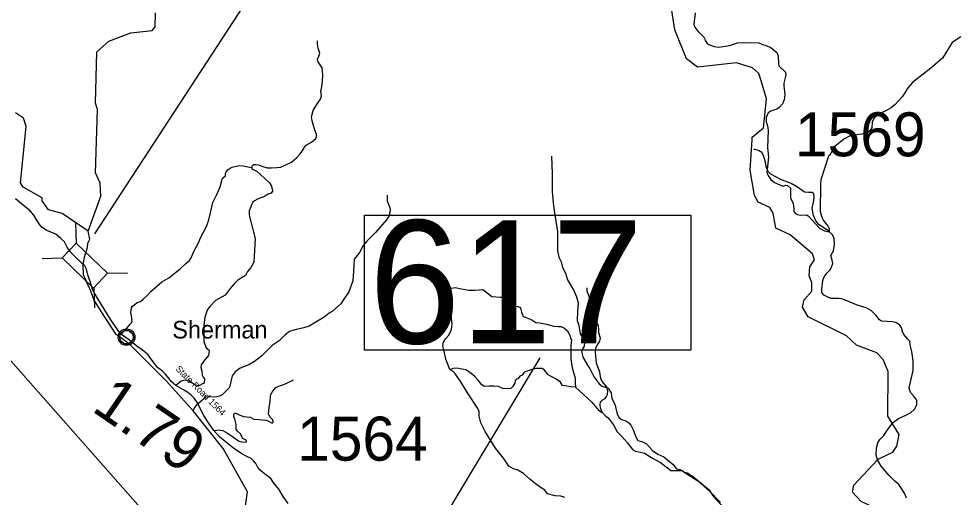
# Model space of a CAD drawing. Extents: x 1248224 to 1454986, y 825081 to 985870.
# Drawn here: x 1308155 to 1318874, y 948203 to 953644 of the extents above; entities that cross this region are included whole.
import ezdxf

# ---------------------------------------------------------------- set-up
doc = ezdxf.new("R2010")
doc.units = 0
for name, color, linetype in [('Exist Civil Demographics Community CELL', 7, 'Continuous'), ('Exist Civil Demographics Community Label', 7, 'Continuous'), ('Exist Hydrographic Creek Single Shore', 7, 'Continuous'), ('Exist Hydrographic Misc Water Feature', 7, 'Continuous'), ('Exist Road Non-System Type 51', 7, 'Continuous'), ('Exist Road Secondary Mileage Hundredths English Label', 7, 'Continuous'), ('Exist Road Secondary Structure Standard Bridge CELL', 7, 'Continuous'), ('Exist Road Secondary Structure Standard Bridge Number Label', 7, 'Continuous'), ('Exist Road Secondary Type 10 Attributed', 7, 'Continuous'), ('Exist Road Secondary Type 51 Attributed', 7, 'Continuous'), ('Exist Road Secondary Type 51 Label', 7, 'Continuous'), ('Exist Road Secondary Type 51 Number Label', 7, 'Continuous')]:
    doc.layers.add(name, color=color, linetype=linetype)

msp = doc.modelspace()

# ---------------------------------------------------------------- linework, layer by layer
at = {"layer": 'Exist Civil Demographics Community CELL'}
msp.add_lwpolyline([(1309304, 950035), (1309305, 950041), (1309307, 950047), (1309310, 950055), (1309313, 950060), (1309316, 950066), (1309320, 950071), (1309324, 950075), (1309328, 950080), (1309334, 950085), (1309339, 950088), (1309344, 950091), (1309349, 950094), (1309355, 950096), (1309360, 950098), (1309365, 950099), (1309369, 950100), (1309374, 950100), (1309380, 950101), (1309384, 950101), (1309390, 950100), (1309395, 950100), (1309400, 950099), (1309405, 950097), (1309410, 950095), (1309417, 950092), (1309423, 950089), (1309428, 950085), (1309433, 950081), (1309436, 950078), (1309441, 950074), (1309444, 950069), (1309448, 950064), (1309451, 950059), (1309453, 950054), (1309455, 950049), (1309457, 950044), (1309458, 950040), (1309459, 950034), (1309460, 950029), (1309460, 950023), (1309460, 950017), (1309459, 950011), (1309458, 950006), (1309457, 950000), (1309455, 949994), (1309452, 949989), (1309449, 949983), (1309446, 949978), (1309443, 949973), (1309438, 949968), (1309433, 949963), (1309428, 949959), (1309423, 949956), (1309419, 949953), (1309412, 949950), (1309405, 949947), (1309399, 949946), (1309392, 949944), (1309388, 949944), (1309383, 949944), (1309378, 949944), (1309373, 949944), (1309368, 949945), (1309362, 949946), (1309357, 949947), (1309352, 949949), (1309347, 949951), (1309344, 949954), (1309337, 949958), (1309331, 949962), (1309326, 949966), (1309322, 949971), (1309319, 949975), (1309316, 949979), (1309312, 949986), (1309310, 949990), (1309308, 949994), (1309306, 950002), (1309304, 950009), (1309303, 950014), (1309303, 950021), (1309303, 950025), (1309303, 950032)], close=True, dxfattribs=at)
for centre, radius in [((1309382, 950023), 94.3), ((1309381, 950023), 76.7)]:
    msp.add_circle(centre, radius, dxfattribs=at)
at = {"layer": 'Exist Hydrographic Creek Single Shore'}
for points in [[(1316504, 952267), (1316507, 952297), (1316634, 952403), (1316667, 952733), (1316613, 952928), (1316582, 953021), (1316508, 953088), (1316326, 953144), (1315883, 953094), (1315759, 953188), (1315625, 953519), (1315560, 953937)], [(1308944, 951228), (1308649, 951428), (1308492, 951473), (1308419, 951573), (1308420, 951606), (1308206, 951729), (1308173, 951778), (1308238, 952421), (1308207, 952513), (1308117, 952574)], [(1318070, 949093), (1318051, 949124), (1318054, 949633), (1317999, 949769), (1317926, 949845), (1317694, 949932), (1317580, 950036), (1317143, 950255), (1317079, 950365), (1317097, 950446), (1317183, 950547), (1317186, 950645), (1317154, 950721), (1317164, 950823), (1317217, 950904), (1317193, 950970), (1316939, 951185), (1316775, 951264), (1316745, 951432), (1316705, 951498), (1316573, 951560), (1316533, 951636), (1316481, 951923), (1316504, 952267)], [(1308887, 950849), (1308902, 950934), (1308935, 951044), (1308941, 951092), (1308964, 951139), (1308944, 951228)], [(1309262, 950054), (1309098, 950312), (1309007, 950452), (1308974, 950547), (1308892, 950733), (1308887, 950849)], [(1311047, 947831), (1310858, 948058), (1310733, 948077), (1310757, 948262), (1310481, 948756), (1310139, 949185), (1309835, 949522), (1309411, 949947), (1309262, 950054)], [(1317921, 947117), (1317896, 947134), (1317947, 947534), (1318087, 947807), (1318114, 947915), (1318050, 948008), (1317745, 948155), (1317647, 948259), (1317665, 948340), (1317879, 948570), (1317939, 948634), (1318041, 948683), (1318108, 948716), (1318151, 948781), (1318179, 948915), (1318070, 949093)]]:
    msp.add_lwpolyline(points, dxfattribs=at)
at = {"layer": 'Exist Hydrographic Misc Water Feature'}
for points in [[(1308944, 951228), (1309087, 951626), (1309082, 951773), (1309027, 951893), (1309052, 952611), (1309028, 952684), (1309042, 953268), (1309178, 953390), (1309431, 953483), (1309673, 953511), (1309707, 953553), (1309711, 953711)], [(1315858, 953711), (1315841, 953580), (1315853, 953548), (1315888, 953503), (1315962, 953429), (1315969, 953397), (1315998, 953360), (1316018, 953347), (1316074, 953330), (1316126, 953323), (1316246, 953340), (1316337, 953372), (1316501, 953376), (1316581, 953370), (1316635, 953347), (1316654, 953346), (1316718, 953317), (1316785, 953263), (1316800, 953223), (1316806, 953134), (1316811, 953111), (1316885, 953037), (1316889, 953005), (1316867, 952913), (1316866, 952881), (1316877, 952783), (1316868, 952723), (1316851, 952676), (1316814, 952636), (1316786, 952617), (1316719, 952595), (1316686, 952573), (1316665, 952522), (1316664, 952473), (1316679, 952425), (1316686, 952373), (1316679, 952181), (1316691, 952071), (1316671, 951895), (1316686, 951862), (1316719, 951818), (1316758, 951781), (1316853, 951742), (1316890, 951752), (1316909, 951747), (1316941, 951718), (1316942, 951608), (1316971, 951544), (1316981, 951484), (1316981, 951452), (1317008, 951422), (1317052, 951412), (1317124, 951414), (1317144, 951402), (1317271, 951263), (1317330, 951233), (1317382, 951220)], [(1318880, 953438), (1318783, 953373), (1318673, 953197), (1318540, 953082), (1318332, 952921), (1318266, 952844), (1318260, 952826), (1318214, 952756), (1318132, 952671), (1318087, 952633), (1318020, 952592), (1317959, 952566), (1317902, 952521), (1317898, 952522), (1317873, 952471), (1317867, 952403), (1317847, 952370), (1317820, 952347), (1317756, 952332), (1317667, 952322), (1317615, 952309), (1317550, 952275), (1317448, 952193), (1317388, 952093), (1317376, 952081), (1317287, 951813), (1317282, 951765), (1317281, 951451), (1317296, 951398), (1317315, 951354), (1317371, 951282), (1317382, 951258), (1317382, 951220)], [(1314219, 952081), (1314228, 951879), (1314227, 951679), (1314242, 951514), (1314289, 951220), (1314290, 951003), (1314304, 950934), (1314329, 950878), (1314347, 950814), (1314378, 950752), (1314404, 950676), (1314475, 950554), (1314506, 950481), (1314524, 950413), (1314516, 950315), (1314514, 950211), (1314529, 950171), (1314548, 950066), (1314556, 950046), (1314583, 950010), (1314598, 949965), (1314593, 949922), (1314562, 949870), (1314576, 949795), (1314641, 949684), (1314657, 949668), (1314705, 949566), (1314763, 949493), (1314798, 949464), (1314866, 949443), (1314901, 949389), (1314909, 949325), (1314940, 949260), (1314969, 949147), (1314986, 949112), (1315018, 949087), (1315065, 949069), (1315101, 949049), (1315124, 949020), (1315151, 948967), (1315181, 948887), (1315202, 948846), (1315250, 948837), (1315301, 948808), (1315372, 948732), (1315431, 948691), (1315498, 948661), (1315606, 948575), (1315645, 948526), (1315685, 948517), (1315736, 948485), (1315768, 948479)], [(1314219, 952081), (1314228, 951879), (1314227, 951679), (1314242, 951514), (1314289, 951220), (1314290, 951003), (1314304, 950934), (1314329, 950878), (1314347, 950814), (1314378, 950752), (1314404, 950676), (1314475, 950554), (1314506, 950481), (1314524, 950413), (1314516, 950315), (1314514, 950211), (1314529, 950171), (1314548, 950066), (1314556, 950046), (1314583, 950010), (1314598, 949965), (1314593, 949922), (1314562, 949870), (1314576, 949795), (1314641, 949684), (1314657, 949668), (1314705, 949566), (1314763, 949493), (1314798, 949464), (1314866, 949443), (1314901, 949389), (1314909, 949325), (1314940, 949260), (1314969, 949147), (1314986, 949112), (1315018, 949087), (1315065, 949069), (1315101, 949049), (1315124, 949020), (1315151, 948967), (1315181, 948887), (1315202, 948846), (1315250, 948837), (1315301, 948808), (1315372, 948732), (1315431, 948691), (1315498, 948661), (1315606, 948575), (1315645, 948526), (1315685, 948517), (1315736, 948485), (1315768, 948479)], [(1312348, 951637), (1312348, 951568), (1312375, 951510), (1312382, 951470), (1312372, 951406), (1312341, 951359), (1312218, 951212), (1312117, 951114), (1312068, 951054), (1312042, 950998), (1312009, 950951), (1311972, 950911), (1311967, 950773), (1311957, 950662), (1311912, 950539), (1311849, 950442), (1311820, 950403), (1311724, 950313), (1311688, 950296), (1311631, 950249), (1311460, 950147), (1311402, 950128), (1311313, 950110), (1311237, 950086), (1311188, 950051), (1311118, 949980), (1311041, 949928), (1310920, 949809), (1310838, 949747), (1310774, 949708), (1310677, 949669), (1310618, 949630), (1310585, 949583), (1310553, 949449), (1310469, 949367), (1310441, 949352), (1310409, 949343), (1310285, 949341), (1310174, 949246), (1310150, 949218), (1310139, 949185)], [(1315768, 948479), (1315776, 948476), (1315788, 948465), (1315823, 948447), (1316014, 948287), (1316056, 948218), (1316158, 948113)]]:
    msp.add_lwpolyline(points, dxfattribs=at)
at = {"layer": 'Exist Road Non-System Type 51'}
for points in [[(1310807, 951953), (1310811, 951969), (1310829, 951987), (1310855, 951987), (1310884, 951982), (1310933, 951963), (1310984, 951949), (1311031, 951948), (1311094, 951953), (1311137, 951958), (1311195, 951984), (1311258, 952014), (1311319, 952067), (1311356, 952103), (1311383, 952138), (1311391, 952159), (1311406, 952186), (1311427, 952208), (1311488, 952242), (1311537, 952284), (1311545, 952303), (1311545, 952331), (1311524, 952379), (1311495, 952482), (1311489, 952531), (1311508, 952603), (1311539, 952659), (1311571, 952702), (1311591, 952730), (1311600, 952763), (1311594, 952820), (1311606, 952874), (1311613, 952931), (1311618, 953009), (1311609, 953085), (1311564, 953155), (1311557, 953184), (1311571, 953221), (1311581, 953252), (1311565, 953310), (1311556, 953355), (1311557, 953395)], [(1309313, 950061), (1309330, 950069), (1309366, 950101), (1309427, 950173), (1309440, 950189), (1309444, 950207), (1309442, 950242), (1309431, 950303), (1309436, 950355), (1309451, 950377), (1309474, 950396), (1309503, 950416), (1309542, 950430), (1309572, 950454), (1309624, 950506), (1309658, 950542), (1309784, 950653), (1309861, 950697), (1309991, 950799), (1310056, 950861), (1310097, 950893), (1310118, 950926), (1310138, 950971), (1310158, 951020), (1310195, 951089), (1310228, 951162), (1310256, 951219), (1310293, 951280), (1310317, 951358), (1310338, 951439), (1310362, 951554), (1310407, 951639), (1310448, 951733), (1310472, 951819), (1310491, 951843), (1310510, 951858), (1310507, 951880), (1310515, 951904), (1310537, 951930), (1310560, 951946), (1310584, 951956), (1310628, 951967), (1310671, 951976), (1310712, 951973), (1310764, 951960), (1310807, 951953)], [(1310807, 951953), (1310808, 951942), (1310822, 951929), (1310869, 951908), (1310954, 951831), (1311008, 951777), (1311030, 951747), (1311039, 951710), (1311043, 951683), (1311030, 951661), (1310993, 951648), (1310944, 951618), (1310898, 951603), (1310871, 951592), (1310838, 951573), (1310819, 951557), (1310805, 951528), (1310795, 951504), (1310779, 951459), (1310779, 951419), (1310785, 951381), (1310846, 951144)], [(1310846, 951144), (1310840, 951012), (1310831, 950875), (1310797, 950814), (1310757, 950769), (1310737, 950724), (1310692, 950696), (1310643, 950667), (1310611, 950635), (1310562, 950578), (1310505, 950500), (1310395, 950439), (1310330, 950370), (1310301, 950329), (1310273, 950247), (1310260, 950162), (1310260, 950035), (1310260, 949974), (1310289, 949901), (1310321, 949876), (1310313, 949815), (1310269, 949762), (1310232, 949709), (1310228, 949678), (1310239, 949636), (1310241, 949591), (1310254, 949568), (1310270, 949547), (1310266, 949500), (1310259, 949497), (1310248, 949490), (1310205, 949470), (1310167, 949475), (1310117, 949506), (1310083, 949527), (1310055, 949532), (1310035, 949531), (1310004, 949524), (1309941, 949471)], [(1314371, 948197), (1314326, 948213), (1314263, 948217), (1314175, 948242), (1314143, 948283), (1314067, 948330), (1313972, 948407), (1313902, 948472), (1313837, 948511), (1313789, 948524), (1313735, 948556), (1313672, 948648), (1313584, 948761), (1313465, 948949), (1313415, 949049), (1313395, 949123), (1313395, 949177), (1313382, 949211), (1313271, 949378), (1313179, 949525), (1313127, 949602), (1313098, 949634), (1313062, 949654), (1313044, 949704), (1313017, 949772), (1312999, 949864), (1312983, 949925), (1312992, 949966), (1313014, 950002), (1313053, 950047), (1313082, 950110), (1313091, 950169), (1313077, 950275), (1313048, 950370), (1313028, 950399), (1313026, 950445), (1313026, 950477), (1313037, 950522), (1313059, 950558), (1313080, 950579), (1313125, 950588), (1313197, 950572), (1313280, 950556), (1313348, 950558), (1313398, 950563), (1313434, 950565), (1313465, 950545), (1313508, 950511), (1313542, 950486), (1313637, 950477), (1313695, 950477), (1313761, 950452)], [(1314796, 949167), (1314777, 949219), (1314775, 949256), (1314779, 949287), (1314799, 949307), (1314831, 949326), (1314847, 949346), (1314858, 949371), (1314863, 949414), (1314849, 949459), (1314797, 949517), (1314781, 949554), (1314770, 949626), (1314732, 949725), (1314721, 949847), (1314725, 949903), (1314743, 949937), (1314770, 949976), (1314777, 950012), (1314761, 950073), (1314759, 950109), (1314757, 950157), (1314734, 950190), (1314705, 950227), (1314687, 950274), (1314687, 950308), (1314689, 950362), (1314662, 950452), (1314626, 950547), (1314626, 950583)], [(1313761, 950452), (1313768, 950425), (1313786, 950400), (1313801, 950375), (1313838, 950373), (1313867, 950360), (1313869, 950353), (1313878, 950308), (1313896, 950256), (1313921, 950251), (1313995, 950220), (1314043, 950188), (1314088, 950186), (1314165, 950170), (1314248, 950147), (1314302, 950145), (1314327, 950145), (1314356, 950132), (1314397, 950098), (1314430, 950044), (1314436, 950015), (1314450, 949988), (1314441, 949932), (1314439, 949866), (1314441, 949771), (1314457, 949674), (1314488, 949555), (1314491, 949503), (1314495, 949453)], [(1314495, 949453), (1314436, 949458), (1314394, 949464), (1314344, 949473), (1314324, 949510), (1314274, 949546), (1314231, 949568), (1314182, 949595), (1314139, 949647), (1314116, 949665), (1314089, 949668), (1314048, 949665), (1313997, 949656), (1313967, 949645), (1313922, 949629), (1313902, 949613), (1313886, 949589), (1313861, 949580), (1313852, 949566), (1313836, 949550), (1313818, 949543), (1313807, 949528), (1313803, 949498), (1313780, 949460), (1313758, 949437), (1313728, 949433), (1313667, 949440), (1313615, 949462), (1313564, 949464), (1313509, 949464), (1313455, 949462), (1313427, 949479), (1313384, 949535), (1313348, 949576), (1313287, 949623), (1313244, 949650), (1313199, 949659), (1313167, 949666), (1313115, 949671), (1313062, 949654)], [(1310377, 948962), (1310408, 948964), (1310426, 948969), (1310479, 948960), (1310531, 948929), (1310586, 948892), (1310634, 948857), (1310663, 948841), (1310709, 948828), (1310746, 948833), (1310742, 948850), (1310707, 948868), (1310691, 948896), (1310683, 948921), (1310646, 948953), (1310628, 948977), (1310628, 949030), (1310613, 949089), (1310604, 949116), (1310604, 949136), (1310610, 949157), (1310624, 949158), (1310665, 949140), (1310713, 949122), (1310790, 949114), (1310830, 949090), (1310889, 949087), (1310968, 949079), (1310973, 949079), (1310999, 949068), (1311039, 949044), (1311052, 949056), (1311047, 949081), (1311012, 949116), (1310997, 949149), (1311006, 949221), (1311017, 949287), (1311021, 949355), (1311025, 949371), (1311041, 949397), (1311063, 949427), (1311083, 949450), (1311103, 949463), (1311151, 949476), (1311199, 949494), (1311283, 949538)], [(1314495, 949453), (1314581, 949373), (1314678, 949285), (1314755, 949192), (1314796, 949167)], [(1314796, 949167), (1314833, 949130), (1314869, 949103), (1314900, 949060), (1314934, 949015), (1314966, 948950), (1315022, 948891), (1315085, 948819), (1315128, 948762), (1315148, 948740), (1315173, 948724), (1315234, 948715), (1315281, 948704), (1315372, 948645), (1315462, 948595), (1315557, 948525), (1315581, 948507), (1315638, 948507), (1315710, 948505), (1315744, 948478), (1315886, 948388), (1316021, 948272), (1316143, 948142)]]:
    msp.add_lwpolyline(points, dxfattribs=at)
at = {"layer": 'Exist Road Secondary Structure Standard Bridge CELL'}
for p, q in [((1308801, 951318), (1308807, 951091)), ((1308421, 950918), (1308647, 950924)), ((1309165, 950749), (1309392, 950754)), ((1309009, 950585), (1309015, 950358))]:
    msp.add_line(p, q, dxfattribs=at)
msp.add_lwpolyline([(1308807, 951091), (1309166, 950749), (1309006, 950582), (1308647, 950924)], close=True, dxfattribs=at)
at = {"layer": 'Exist Road Secondary Structure Standard Bridge Number Label'}
msp.add_line((1309019, 951197), (1312285, 956192), dxfattribs=at)
for points in [[(1311436, 945141), (1311012, 946414), (1306982, 950975), (1306487, 954475)], [(1311311, 947403), (1311959, 947293), (1312875, 947766), (1314091, 949788)]]:
    msp.add_lwpolyline(points, dxfattribs=at)
msp.add_lwpolyline([(1312091, 951409), (1315807, 951409), (1315807, 949873), (1312091, 949873)], close=True, dxfattribs=at)
at = {"layer": 'Exist Road Secondary Type 10 Attributed'}
for points in [[(1318065, 948448), (1317973, 948557), (1317932, 948629), (1317919, 948679), (1317920, 948763), (1317935, 948819), (1317961, 948858), (1318005, 948904), (1318055, 948981), (1318116, 949054), (1318170, 949099), (1318256, 949135), (1318310, 949163), (1318355, 949204), (1318381, 949251), (1318379, 949307), (1318346, 949351), (1318307, 949394), (1318294, 949447), (1318317, 949544), (1318337, 949643), (1318340, 949753), (1318322, 949860), (1318304, 949936), (1318299, 949977), (1318276, 950002), (1318232, 950053), (1318216, 950086), (1318206, 950130), (1318187, 950161), (1318143, 950191), (1318099, 950199), (1318041, 950202), (1317979, 950203), (1317955, 950218), (1317912, 950273), (1317861, 950326), (1317804, 950358), (1317711, 950383), (1317537, 950456), (1317493, 950464), (1317403, 950464), (1317358, 950481), (1317323, 950502), (1317298, 950531), (1317300, 950570), (1317311, 950667), (1317326, 950709), (1317359, 950753), (1317394, 950787), (1317414, 950829), (1317423, 950862), (1317415, 950898), (1317402, 950950), (1317430, 951006), (1317443, 951077), (1317438, 951149), (1317418, 951191), (1317368, 951238), (1317268, 951302), (1317230, 951347), (1317203, 951405), (1317189, 951485), (1317209, 951578), (1317212, 951620), (1317209, 951655), (1317190, 951668), (1317146, 951667), (1317100, 951674), (1317021, 951728), (1316950, 951772), (1316831, 951816), (1316718, 951876), (1316684, 951910), (1316665, 951963), (1316658, 952015), (1316635, 952089), (1316616, 952122), (1316577, 952145), (1316524, 952163)], [(1318264, 948191), (1318244, 948240), (1318214, 948288), (1318176, 948346), (1318131, 948385), (1318065, 948448)]]:
    msp.add_lwpolyline(points, dxfattribs=at)
at = {"layer": 'Exist Road Secondary Type 51 Attributed'}
for points in [[(1308887, 950849), (1308772, 950958), (1308740, 950996), (1308706, 951047), (1308676, 951109), (1308634, 951145), (1308575, 951194), (1308473, 951236), (1308419, 951270), (1308393, 951302), (1308364, 951346), (1308324, 951410), (1308285, 951461), (1308184, 951541), (1308116, 951597)], [(1311221, 948130), (1311166, 948210), (1311117, 948293), (1311052, 948374), (1311024, 948414), (1310994, 948439), (1310954, 948469), (1310903, 948509), (1310877, 948540), (1310855, 948586), (1310828, 948616), (1310802, 948644), (1310752, 948665), (1310694, 948697), (1310601, 948760), (1310504, 948834), (1310440, 948889), (1310377, 948962), (1310315, 949048), (1310261, 949132), (1310231, 949189), (1310189, 949274), (1310153, 949327), (1310119, 949361), (1310081, 949393), (1310022, 949427), (1309941, 949471), (1309889, 949517), (1309861, 949557), (1309823, 949604), (1309789, 949634), (1309734, 949676), (1309698, 949723), (1309662, 949771), (1309626, 949822), (1309561, 949877), (1309497, 949922), (1309414, 949990), (1309313, 950061), (1309277, 950108), (1309203, 950218), (1309135, 950330), (1309040, 950485), (1308994, 950564), (1308971, 950645), (1308941, 950732), (1308926, 950797), (1308905, 950833), (1308887, 950849)]]:
    msp.add_lwpolyline(points, dxfattribs=at)

# ---------------------------------------------------------------- texts
at = {"layer": 'Exist Civil Demographics Community Label'}
msp.add_text('Sherman', height=200, dxfattribs=at).set_placement((1309902, 950008))
at = {"layer": 'Exist Road Secondary Mileage Hundredths English Label'}
msp.add_text('1.79', height=500, rotation=325.6899, dxfattribs=at).set_placement((1308971, 949190))
at = {"layer": 'Exist Road Secondary Structure Standard Bridge Number Label'}
msp.add_text('617', height=1400, dxfattribs=at).set_placement((1312141, 949952))
at = {"layer": 'Exist Road Secondary Type 51 Label'}
msp.add_text('State Road 1564', height=75, rotation=314.9302, dxfattribs=at).set_placement((1309934, 949655))
at = {"layer": 'Exist Road Secondary Type 51 Number Label'}
for s, p in [('1569', (1316993, 952080)), ('1564', (1311324, 948618))]:
    msp.add_text(s, height=500, dxfattribs=at).set_placement(p)

doc.saveas('drawing.dxf')
